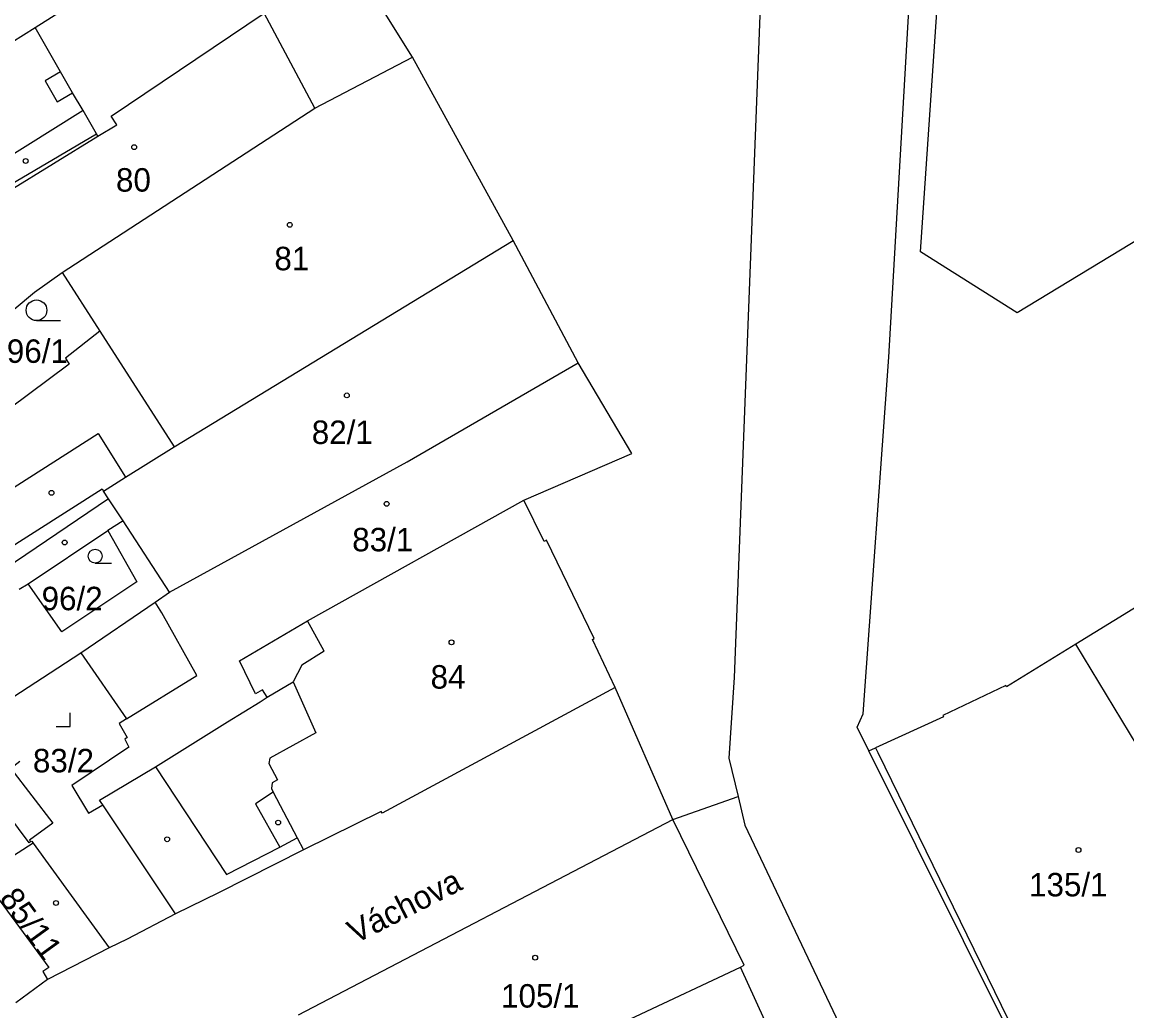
# Model space of a CAD drawing. Extents: x -679220 to -673243, y -1075091 to -1066557.
# Drawn here: x -676420.8 to -676340.7, y -1071747.9 to -1071676.2 of the extents above; entities that cross this region are included whole.
import ezdxf

# ---------------------------------------------------------------- set-up
doc = ezdxf.new("R2010")
doc.units = 0
for name, color, linetype in [('Hranice parcel', 7, 'Continuous'), ('Parcelní čísla', 7, 'Continuous'), ('Pop  PČ popisy', 7, 'Continuous'), ('Vnitřní kresba', 7, 'Continuous'), ('Značky budov', 7, 'Continuous'), ('Značky kultur', 7, 'Continuous')]:
    doc.layers.add(name, color=color, linetype=linetype)

msp = doc.modelspace()

# ---------------------------------------------------------------- linework, layer by layer
at = {"layer": 'Hranice parcel'}
for p, q in [((-676392.51, -1071678.79), (-676396.92, -1071671.69)), ((-676385.21, -1071692.07), (-676392.51, -1071678.79)), ((-676380.51, -1071700.93), (-676385.21, -1071692.07)), ((-676338.4, -1071717.62), (-676344.43, -1071721.33)), ((-676423.39, -1071726.4), (-676416.55, -1071721.95)), ((-676416.55, -1071721.95), (-676413.24, -1071726.75)), ((-676373.64, -1071734.03), (-676377.83, -1071724.46)), ((-676359.43, -1071729.07), (-676358.95, -1071728.85)), ((-676325.68, -1071796.83), (-676359.43, -1071729.07)), ((-676373.64, -1071734.03), (-676368.92, -1071732.38)), ((-676415.99, -1071733.59), (-676414.96, -1071732.98)), ((-676409.68, -1071740.88), (-676414.96, -1071732.98)), ((-676400.77, -1071748.19), (-676373.64, -1071734.03)), ((-676420, -1071735.76), (-676423.74, -1071738.14)), ((-676420.26, -1071735.53), (-676420.18, -1071735.64)), ((-676420, -1071735.76), (-676414.5, -1071743.34)), ((-676414.5, -1071743.34), (-676418.96, -1071745.63)), ((-676365.46, -1071751.88), (-676368.75, -1071744.75)), ((-676418.96, -1071745.63), (-676421.27, -1071747.32))]:
    msp.add_line(p, q, dxfattribs=at)
for points in [[(-676409.82, -1071487.07), (-676395.79, -1071511.68), (-676384.03, -1071532.68), (-676381.89, -1071539.87), (-676376.19, -1071569.34), (-676368.13, -1071616.48), (-676365.86, -1071630.87), (-676366.52, -1071654.54), (-676369.19, -1071723.74), (-676369.58, -1071729.58), (-676368.92, -1071732.38)], [(-676359.43, -1071729.07), (-676360.28, -1071727.35), (-676359.84, -1071726.37), (-676357.99, -1071700.53), (-676354.68, -1071643.07)], [(-676449.45, -1071696.12), (-676449.16, -1071695.9), (-676445.73, -1071693.47), (-676439.3, -1071688.9), (-676434.63, -1071685.95), (-676431.25, -1071683.83), (-676429.61, -1071682.8), (-676428.7, -1071682.09), (-676427.79, -1071681.54), (-676426.64, -1071680.89), (-676419.86, -1071676.64), (-676407.57, -1071668.83), (-676400.92, -1071664.77)], [(-676443.91, -1071702.66), (-676436.71, -1071697.18), (-676432.26, -1071694.25), (-676426.37, -1071691.03), (-676425.39, -1071690.51), (-676425.06, -1071690.34), (-676424.98, -1071690.46), (-676415.31, -1071684.52), (-676413.94, -1071683.68), (-676414.36, -1071683.06), (-676403.27, -1071675.59), (-676403.19, -1071675.52), (-676396.92, -1071671.69)], [(-676417.9, -1071694.39), (-676399.59, -1071682.48), (-676392.51, -1071678.79)], [(-676429.04, -1071719.44), (-676422.39, -1071714.77), (-676415, -1071710.08), (-676414.9, -1071710.24), (-676413.31, -1071709.22), (-676409.79, -1071707.02), (-676385.21, -1071692.07)], [(-676424.82, -1071699.49), (-676421.37, -1071697.06), (-676419.9, -1071695.81), (-676417.9, -1071694.39)], [(-676417.9, -1071694.39), (-676415.17, -1071698.64), (-676417.67, -1071700.59), (-676417.39, -1071701.04), (-676421.76, -1071704.3), (-676423.6, -1071701.41), (-676424.82, -1071699.49)], [(-676416.55, -1071721.95), (-676411.17, -1071718.28), (-676410.12, -1071717.56), (-676392.9, -1071708.11), (-676380.51, -1071700.93)], [(-676384.44, -1071710.9), (-676376.61, -1071707.51), (-676380.51, -1071700.93)], [(-676414.96, -1071732.98), (-676415.19, -1071732.64), (-676411.13, -1071730.23), (-676405.92, -1071726.95), (-676403.56, -1071725.5), (-676403.04, -1071725.17), (-676403.37, -1071724.64), (-676403.9, -1071724.92), (-676405.06, -1071722.54), (-676400.12, -1071719.64), (-676384.44, -1071710.9)], [(-676377.83, -1071724.46), (-676379.46, -1071720.98), (-676379.34, -1071720.92), (-676382.8, -1071713.8), (-676382.97, -1071713.88), (-676384.44, -1071710.9)], [(-676417.93, -1071720.44), (-676420.37, -1071716.95), (-676414.6, -1071713.1), (-676412.5, -1071716.81), (-676417.93, -1071720.44)], [(-676344.43, -1071721.33), (-676349.47, -1071724.43), (-676349.51, -1071724.33), (-676354.08, -1071726.49), (-676354.03, -1071726.6), (-676358.95, -1071728.85)], [(-676322.2, -1071742.93), (-676329.1, -1071747.9), (-676330.64, -1071745.35), (-676331.1, -1071744.58), (-676330.4, -1071744.07), (-676334.1, -1071737.92), (-676334.77, -1071736.82), (-676334.99, -1071736.94), (-676344.43, -1071721.33)], [(-676377.83, -1071724.46), (-676394.72, -1071733.57), (-676394.77, -1071733.46), (-676400.41, -1071736.23), (-676406.58, -1071739.36), (-676409.68, -1071740.88)], [(-676413.24, -1071726.75), (-676413.78, -1071727.08), (-676413.2, -1071728.1), (-676413.37, -1071728.22), (-676413.07, -1071728.79), (-676417.21, -1071731.58), (-676415.99, -1071733.59)], [(-676358.95, -1071728.85), (-676358.78, -1071729.17), (-676348.35, -1071750.57), (-676338.79, -1071768.68)], [(-676420.97, -1071729.84), (-676421.63, -1071730.33), (-676418.58, -1071734.3), (-676420.26, -1071735.53)], [(-676420.18, -1071735.64), (-676420.3, -1071735.72), (-676422.7, -1071732.52)], [(-676368.92, -1071732.38), (-676368.43, -1071734.45), (-676360.46, -1071751.23), (-676343.97, -1071784.01), (-676336.24, -1071800.05)], [(-676368.75, -1071744.75), (-676368.47, -1071744.59), (-676373.64, -1071734.03)], [(-676420.18, -1071735.64), (-676420.11, -1071735.6), (-676420, -1071735.76)], [(-676423.74, -1071738.14), (-676418.87, -1071744.77), (-676419.3, -1071745.06), (-676418.96, -1071745.63)], [(-676409.68, -1071740.88), (-676413.2, -1071742.71), (-676414.5, -1071743.34)], [(-676395.26, -1071757.96), (-676391.1, -1071755.73), (-676389.76, -1071755.06), (-676386.42, -1071753.23), (-676384.86, -1071752.38), (-676383.97, -1071751.9), (-676368.75, -1071744.75)]]:
    msp.add_lwpolyline(points, dxfattribs=at)
at = {"layer": 'Vnitřní kresba'}
for p, q in [((-676355.69, -1071692.9), (-676352.5, -1071646.08)), ((-676306.9, -1071671.93), (-676348.68, -1071697.31)), ((-676399.59, -1071682.48), (-676403.27, -1071675.59)), ((-676418.01, -1071679.84), (-676419.86, -1071676.64)), ((-676418.01, -1071679.84), (-676419.14, -1071680.49)), ((-676419.14, -1071680.49), (-676418.26, -1071682.01)), ((-676417.14, -1071681.36), (-676418.01, -1071679.84)), ((-676418.26, -1071682.01), (-676417.14, -1071681.36)), ((-676416.39, -1071682.66), (-676417.14, -1071681.36)), ((-676416.39, -1071682.66), (-676426, -1071688.65)), ((-676415.41, -1071684.35), (-676416.39, -1071682.66)), ((-676425.13, -1071690.06), (-676415.41, -1071684.35)), ((-676415.31, -1071684.52), (-676415.41, -1071684.35)), ((-676348.68, -1071697.31), (-676355.69, -1071692.9)), ((-676415.17, -1071698.64), (-676409.79, -1071707.02)), ((-676424.17, -1071711.73), (-676415.28, -1071706.05)), ((-676415.28, -1071706.05), (-676413.31, -1071709.22)), ((-676414.54, -1071710.8), (-676414.9, -1071710.24)), ((-676414.54, -1071710.8), (-676422.04, -1071715.88)), ((-676413.49, -1071712.4), (-676414.54, -1071710.8)), ((-676413.49, -1071712.4), (-676414.6, -1071713.1)), ((-676410.12, -1071717.56), (-676413.49, -1071712.4)), ((-676421.01, -1071717.35), (-676420.37, -1071716.95)), ((-676410.68, -1071719.06), (-676411.17, -1071718.28)), ((-676408.13, -1071723.6), (-676410.68, -1071719.06)), ((-676398.91, -1071721.83), (-676400.12, -1071719.64)), ((-676398.91, -1071721.83), (-676400.52, -1071722.85)), ((-676400.52, -1071722.85), (-676401.15, -1071724.06)), ((-676413.24, -1071726.75), (-676408.13, -1071723.6)), ((-676403.04, -1071725.17), (-676401.15, -1071724.06)), ((-676401.15, -1071724.06), (-676399.51, -1071727.76)), ((-676399.51, -1071727.76), (-676402.86, -1071729.6)), ((-676411.13, -1071730.23), (-676405.98, -1071738.03)), ((-676402.86, -1071729.6), (-676402.93, -1071729.97)), ((-676402.93, -1071729.97), (-676402.3, -1071731.16)), ((-676402.67, -1071731.37), (-676402.74, -1071731.79)), ((-676402.74, -1071731.79), (-676402.6, -1071732.06)), ((-676402.3, -1071731.16), (-676402.67, -1071731.37)), ((-676402.6, -1071732.06), (-676403.9, -1071732.9)), ((-676402.6, -1071732.06), (-676400.86, -1071735.37)), ((-676403.9, -1071732.9), (-676402.13, -1071736.04)), ((-676402.13, -1071736.04), (-676400.86, -1071735.37)), ((-676400.86, -1071735.37), (-676400.41, -1071736.23)), ((-676405.98, -1071738.03), (-676402.13, -1071736.04))]:
    msp.add_line(p, q, dxfattribs=at)
at = {"layer": 'Značky budov'}
for centre in [(-676412.687, -1071685.309), (-676420.547, -1071686.309), (-676401.407, -1071690.939), (-676397.267, -1071703.299), (-676418.677, -1071710.359), (-676394.387, -1071711.159), (-676417.717, -1071713.959), (-676389.687, -1071721.199), (-676402.247, -1071734.259), (-676410.287, -1071735.469), (-676344.247, -1071736.249), (-676418.347, -1071740.089), (-676383.617, -1071744.049)]:
    msp.add_circle(centre, 0.175, dxfattribs=at)
at = {"layer": 'Značky kultur'}
for p, q in [((-676419.763, -1071697.88), (-676418.013, -1071697.88)), ((-676415.505, -1071715.45), (-676414.333, -1071715.45)), ((-676417.33, -1071727.3), (-676417.33, -1071726.3)), ((-676418.331, -1071727.3), (-676417.33, -1071727.3))]:
    msp.add_line(p, q, dxfattribs=at)
for centre, radius in [((-676419.763, -1071697.13), 0.75), ((-676415.505, -1071714.947), 0.502)]:
    msp.add_circle(centre, radius, dxfattribs=at)

# ---------------------------------------------------------------- texts
at = {"layer": 'Parcelní čísla'}
for s, p in [('80', (-676414, -1071688.529)), ('81', (-676402.52, -1071694.229)), ('96/1', (-676421.91, -1071700.94)), ('82/1', (-676399.81, -1071706.82)), ('83/1', (-676396.88, -1071714.6)), ('96/2', (-676419.39, -1071718.87)), ('84', (-676391.2, -1071724.55)), ('83/2', (-676420.02, -1071730.62)), ('135/1', (-676347.828, -1071739.61)), ('105/1', (-676386.09, -1071747.67))]:
    msp.add_text(s, height=1.7, dxfattribs=at).set_placement(p)
msp.add_text('85/11', height=1.7, rotation=306, dxfattribs=at).set_placement((-676422.517, -1071739.779))
at = {"layer": 'Pop  PČ popisy'}
msp.add_text('Váchova', height=1.7, rotation=27, dxfattribs=at).set_placement((-676396.657, -1071743.073))

doc.saveas('drawing.dxf')
